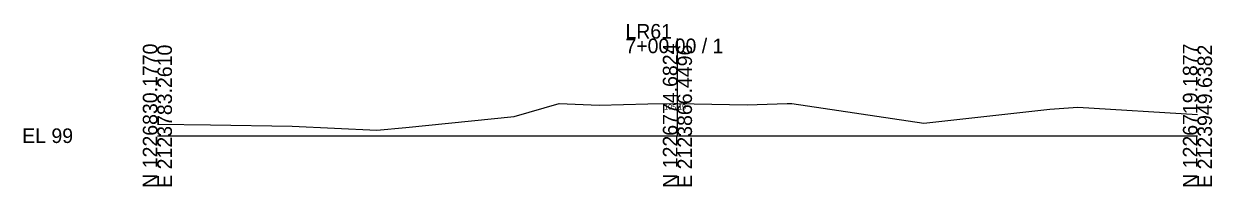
# Model space of a CAD drawing. Extents: x 2126751 to 2128979, y 1225108 to 1234639.
# Drawn here: x 2126750.9 to 2126979.4, y 1232107.5 to 1232138.7 of the extents above; entities that cross this region are included whole.
import ezdxf

# ---------------------------------------------------------------- set-up
doc = ezdxf.new("R2010")
doc.units = 0
for name, color, linetype in [('XS_CELL', 7, 'Continuous'), ('XS_X_GROUND', 7, 'Continuous'), ('XS_X_GROUND_TX', 7, 'Continuous')]:
    doc.layers.add(name, color=color, linetype=linetype)

msp = doc.modelspace()

# ---------------------------------------------------------------- linework, layer by layer
at = {"layer": 'XS_CELL'}
for p, q in [((2126876.61, 1232117.21), (2126876.61, 1232135.86)), ((2126776.61, 1232117.21), (2126876.61, 1232117.21)), ((2126876.61, 1232117.21), (2126976.61, 1232117.21))]:
    msp.add_line(p, q, dxfattribs=at)
at = {"layer": 'XS_X_GROUND'}
for p, q in [((2126845.22, 1232120.88), (2126853.89, 1232123.38)), ((2126853.89, 1232123.38), (2126861.57, 1232123.08)), ((2126861.57, 1232123.08), (2126870.94, 1232123.31)), ((2126870.94, 1232123.31), (2126875.96, 1232123.41)), ((2126875.96, 1232123.41), (2126876.61, 1232123.4)), ((2126876.61, 1232123.4), (2126879.81, 1232123.33)), ((2126879.81, 1232123.33), (2126890.05, 1232123.11)), ((2126890.05, 1232123.11), (2126897.74, 1232123.42)), ((2126897.74, 1232123.42), (2126898.59, 1232123.38)), ((2126898.59, 1232123.38), (2126923.96, 1232119.6)), ((2126923.96, 1232119.6), (2126948.22, 1232122.31)), ((2126948.22, 1232122.31), (2126953.62, 1232122.71)), ((2126953.62, 1232122.71), (2126976.61, 1232121.31)), ((2126824.36, 1232118.76), (2126845.22, 1232120.88)), ((2126776.61, 1232119.4), (2126786.83, 1232119.32)), ((2126786.83, 1232119.32), (2126802.5, 1232119.02)), ((2126802.5, 1232119.02), (2126818.79, 1232118.27)), ((2126818.79, 1232118.27), (2126824.36, 1232118.76))]:
    msp.add_line(p, q, dxfattribs=at)

# ---------------------------------------------------------------- texts
at = {"layer": 'XS_CELL'}
for s, p in [('LR61', (2126866.61, 1232135.86)), ('7+00.00 / 1', (2126866.61, 1232133.06)), ('EL 99', (2126750.61, 1232115.81))]:
    msp.add_text(s, height=2.8, dxfattribs=at).set_placement(p)
for s, p in [('N 1226830.1770', (2126776.61, 1232107.21)), ('E 2123783.2610', (2126779.41, 1232107.21)), ('N 1226774.6824', (2126876.61, 1232107.21)), ('E 2123866.4496', (2126879.41, 1232107.21)), ('N 1226719.1877', (2126976.61, 1232107.21)), ('E 2123949.6382', (2126979.41, 1232107.21))]:
    msp.add_text(s, height=2.8, rotation=90, dxfattribs=at).set_placement(p)
at = {"layer": 'XS_X_GROUND_TX'}
msp.add_text('105.19', height=1, dxfattribs=at).set_placement((2126874.05, 1232122.24))

doc.saveas('drawing.dxf')
